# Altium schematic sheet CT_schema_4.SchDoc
size 300 x 247 mm
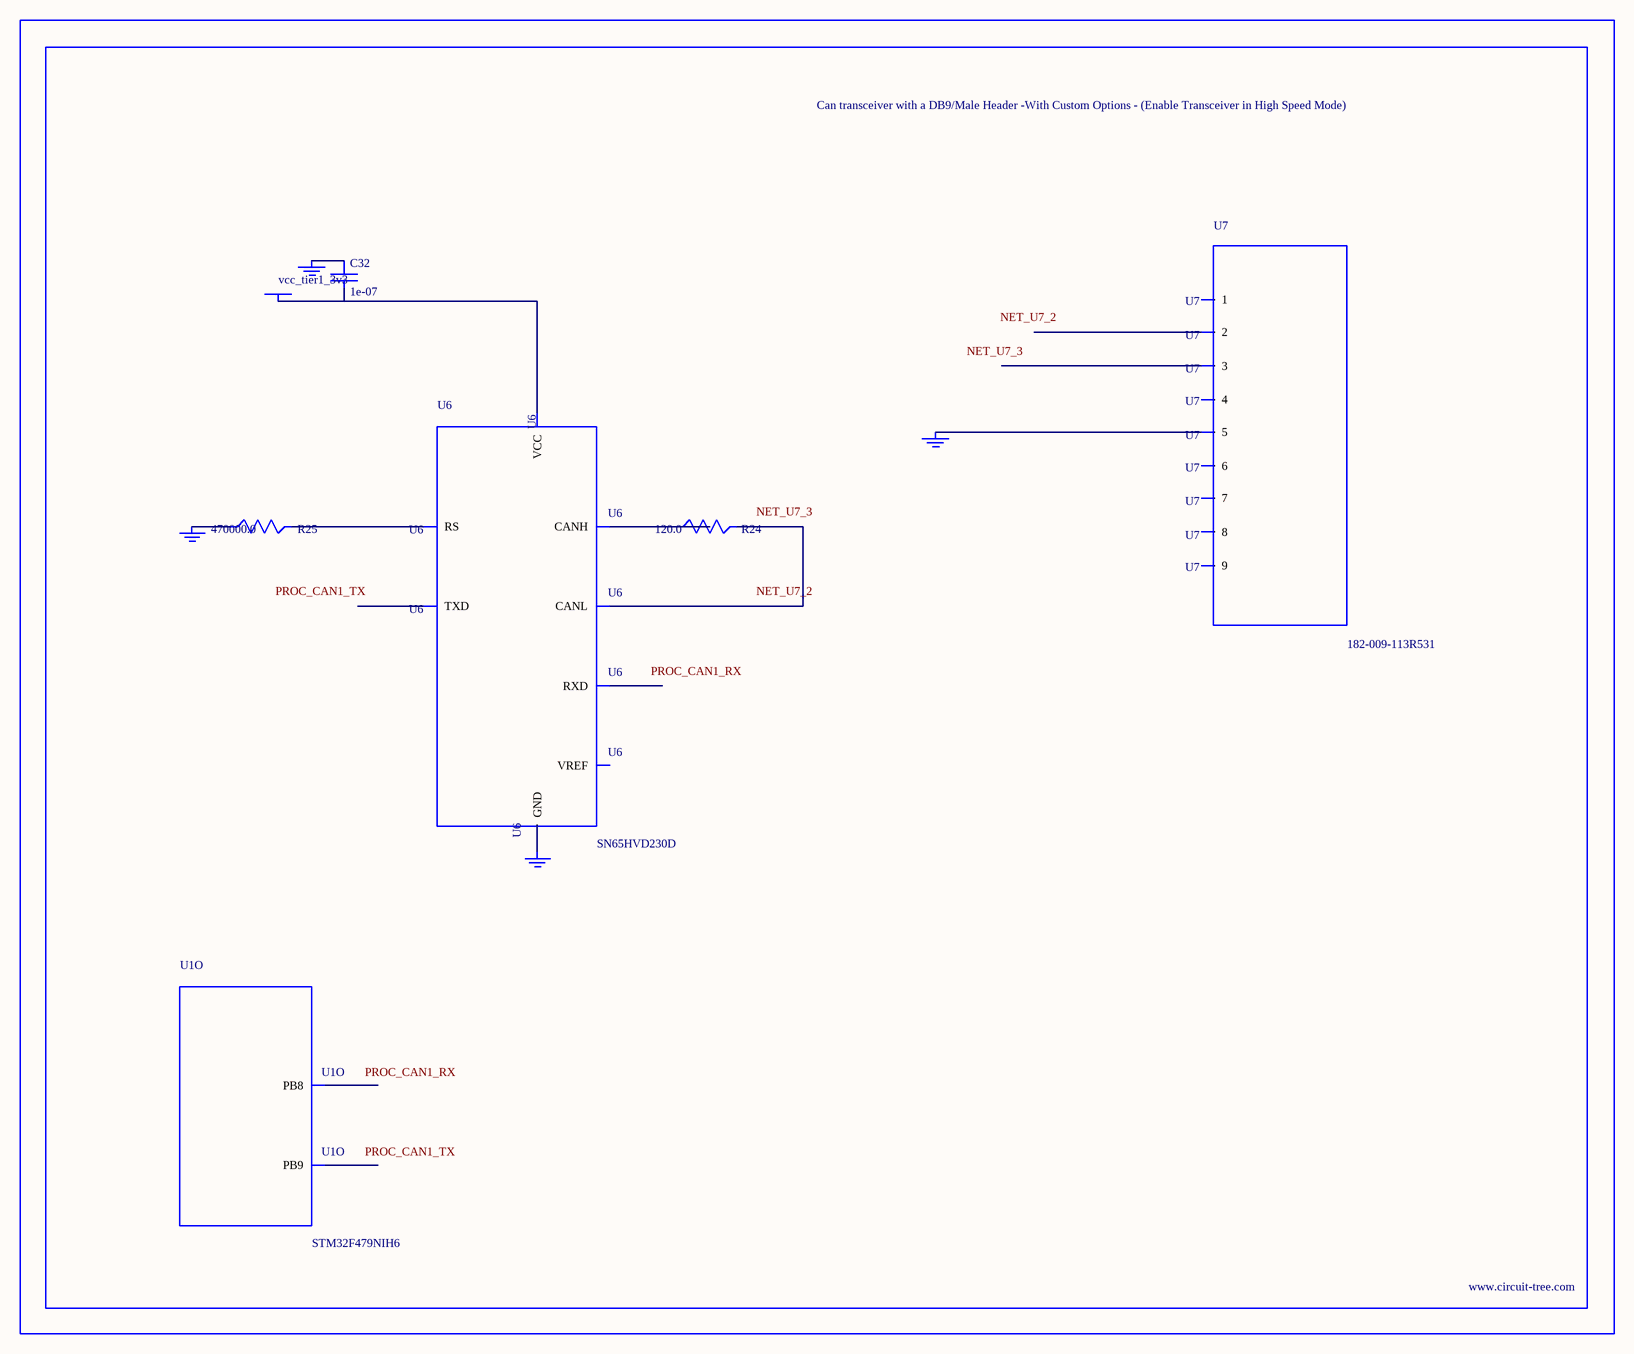
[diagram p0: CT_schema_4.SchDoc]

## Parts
BORDER3  (no value)
C32  1e-07  [C0402]
GND_INSTANCE_3_0  (no value)
GND_INSTANCE_3_1  (no value)
GND_INSTANCE_3_2  (no value)
GND_INSTANCE_3_3  (no value)
POWER_INSTANCE_3_0  vcc_tier1_3v3
R24  120.0  [R0603]
R25  470000.0  [R0603]
U1  STM32F479NIH6  [TFBGA216]  (part O of 17)
U6  SN65HVD230D  [SOIC-8]
U7  182-009-113R531  [182-009-MALE]

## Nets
NetC32_1: C32.1 GND_INSTANCE_3_0.0(GND)
NetC32_2: C32.2 POWER_INSTANCE_3_0.0(PWR) U6.3(VCC)
NetGND_INSTANCE_3_1_0: GND_INSTANCE_3_1.0(GND) R25.1
NetGND_INSTANCE_3_2_0: GND_INSTANCE_3_2.0(GND) U6.2(GND)
NetGND_INSTANCE_3_3_0: GND_INSTANCE_3_3.0(GND) U7.5
NetR24_1: R24.1 U6.7(CANH)
NetR24_2: R24.2 U6.6(CANL)
NetR25_2: R25.2 U6.8(RS)

Not connected (* = marked no-connect by the designer): U1 A7(PB8) B4(PB9); U6 1(TXD) 4(RXD) 5(VREF); U7 1 2 3 4 6 7 8 9

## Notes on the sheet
- Labels drawn without touching a wire or pin: NET_U7_2, NET_U7_3, PROC_CAN1_RX, PROC_CAN1_TX

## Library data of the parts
BORDER3 = BORDER_PAGE3
C32 = C0402C104K3RACTU
GND_INSTANCE_3_0-GND_INSTANCE_3_3 = GND
POWER_INSTANCE_3_0 = PWR
R24 = RC0603JR-07120RL
R25 = RC0603JR-07470KL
